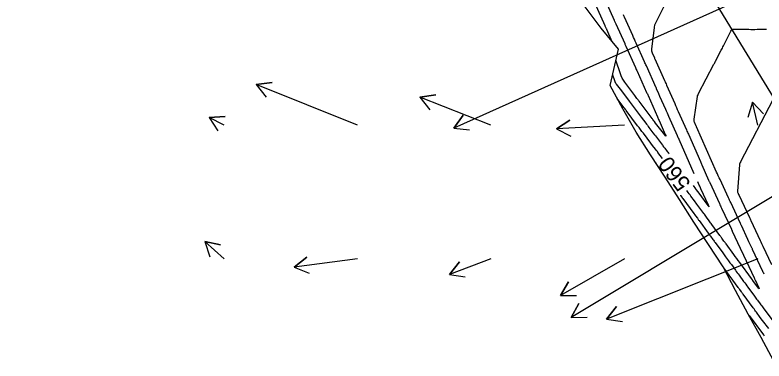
# Model space of a CAD drawing. Extents: x 954385 to 988206, y 1868364 to 1924553.
# Drawn here: x 956878.8 to 957159.4, y 1920780.6 to 1920910.1 of the extents above; entities that cross this region are included whole.
import ezdxf

# ---------------------------------------------------------------- set-up
doc = ezdxf.new("R2010")
doc.units = 0
for name, color, linetype in [('24', 7, 'Continuous'), ('26', 7, 'Continuous'), ('5', 7, 'Continuous'), ('6', 7, 'Continuous'), ('7', 7, 'Continuous'), ('Default', 7, 'Continuous')]:
    doc.layers.add(name, color=color, linetype=linetype)

msp = doc.modelspace()

# ---------------------------------------------------------------- linework, layer by layer
at = {"layer": '24'}
msp.add_lwpolyline([(957163.12, 1920780.62), (957158.31, 1920789.4), (957153.5, 1920798.19), (957148.78, 1920807.02), (957144.15, 1920815.91), (957138.58, 1920824.23), (957133.17, 1920832.64), (957127.8, 1920841.08), (957122.33, 1920849.45), (957116.87, 1920857.84), (957111.47, 1920866.26), (957106.54, 1920874.96), (957101.74, 1920883.75), (957104.85, 1920897.38), (957098.4, 1920905.15), (957092.36, 1920913.18)], dxfattribs=at)
at = {"layer": '26'}
for points in [[(957157.13, 1920918.93), (957043.17, 1920867.81), (957046.68, 1920872.67), (957043.17, 1920867.81), (957049.13, 1920867.2)], [(957007.13, 1920868.93), (956969.15, 1920884.07), (956975.09, 1920884.93), (956969.15, 1920884.07), (956972.87, 1920879.36)], [(957057.13, 1920868.93), (957030.49, 1920879.36), (957036.42, 1920880.26), (957030.49, 1920879.36), (957034.23, 1920874.67)], [(957157.13, 1920868.93), (957155.14, 1920877.47), (957159.24, 1920873.09), (957155.14, 1920877.47), (957153.4, 1920871.73)], [(956957.13, 1920868.93), (956951.55, 1920871.78), (956957.54, 1920872.09), (956951.55, 1920871.78), (956954.81, 1920866.74)], [(957107.13, 1920868.93), (957081.65, 1920867.47), (957086.66, 1920870.76), (957081.65, 1920867.47), (957087, 1920864.77)], [(957207.13, 1920868.93), (957087.13, 1920796.9), (957090.04, 1920802.14), (957087.13, 1920796.9), (957093.13, 1920797)], [(956957.13, 1920818.93), (956949.95, 1920825.3), (956955.83, 1920824.09), (956949.95, 1920825.3), (956951.85, 1920819.6)], [(957007.13, 1920818.93), (956983.42, 1920815.77), (956988.18, 1920819.43), (956983.42, 1920815.77), (956988.97, 1920813.48)], [(957057.13, 1920818.93), (957041.56, 1920813.05), (957045.36, 1920817.69), (957041.56, 1920813.05), (957047.48, 1920812.08)], [(957107.13, 1920818.93), (957083.18, 1920805.09), (957086.18, 1920810.29), (957083.18, 1920805.09), (957089.18, 1920805.09)], [(957157.13, 1920818.93), (957100.44, 1920796.32), (957104.15, 1920801.03), (957100.44, 1920796.32), (957106.38, 1920795.46)]]:
    msp.add_lwpolyline(points, dxfattribs=at)
at = {"layer": '6'}
for points in [[(957125.98, 1920921.71), (957118.38, 1920906.33), (957118.36, 1920906.29), (957118.35, 1920906.26), (957118.34, 1920906.22), (957118.34, 1920906.19), (957118.27, 1920905.68), (957118.26, 1920905.58), (957118.25, 1920905.48), (957117.28, 1920897.39), (957117.26, 1920897.02), (957117.29, 1920896.67), (957117.37, 1920896.32), (957117.49, 1920895.98), (957118.33, 1920894.13), (957118.37, 1920894.04), (957118.41, 1920893.95), (957118.45, 1920893.86), (957118.49, 1920893.77), (957122.17, 1920885.56), (957122.35, 1920885.15), (957122.53, 1920884.75), (957122.71, 1920884.34), (957122.89, 1920883.93), (957125.96, 1920877), (957126.29, 1920876.26), (957126.62, 1920875.52), (957126.94, 1920874.78), (957127.27, 1920874.05), (957130.33, 1920867.13), (957130.52, 1920866.71), (957130.7, 1920866.3), (957130.89, 1920865.88), (957131.07, 1920865.47), (957135.59, 1920855.25), (957136, 1920854.33), (957136.13, 1920854.03), (957138.68, 1920848.27), (957138.77, 1920848.06), (957138.87, 1920847.85), (957138.97, 1920847.64), (957139.06, 1920847.43), (957142.72, 1920839.55), (957142.91, 1920839.13), (957143.1, 1920838.72), (957143.3, 1920838.3), (957143.49, 1920837.89), (957147.21, 1920829.94), (957147.29, 1920829.77), (957147.37, 1920829.6), (957147.45, 1920829.44), (957147.53, 1920829.27), (957151.51, 1920820.76), (957151.57, 1920820.62), (957151.63, 1920820.49), (957151.7, 1920820.36), (957151.76, 1920820.22), (957155.73, 1920811.75), (957155.81, 1920811.56), (957155.9, 1920811.38), (957155.99, 1920811.19), (957156.07, 1920811.01), (957157.47, 1920807.99), (957157.57, 1920807.74), (957157.58, 1920807.65), (957157.51, 1920807.71), (957157.34, 1920807.91), (957155.22, 1920810.78), (957155.18, 1920810.84), (957155.13, 1920810.91), (957155.09, 1920810.97), (957155.04, 1920811.03), (957154.68, 1920811.53), (957150.3, 1920817.5), (957149.75, 1920818.25), (957149.2, 1920819), (957148.65, 1920819.75), (957148.1, 1920820.5), (957145.18, 1920824.48), (957144.99, 1920824.74), (957144.8, 1920825), (957144.61, 1920825.26), (957144.41, 1920825.52), (957143.65, 1920826.57), (957143.45, 1920826.83), (957143.26, 1920827.09), (957143.07, 1920827.35), (957142.88, 1920827.61), (957139.89, 1920831.69), (957139.64, 1920832.04), (957139.38, 1920832.39), (957139.12, 1920832.74), (957138.87, 1920833.09), (957137.84, 1920834.48), (957137.59, 1920834.83), (957137.33, 1920835.18), (957137.07, 1920835.53), (957136.81, 1920835.88), (957134.62, 1920838.86), (957134.29, 1920839.3), (957133.97, 1920839.74), (957133.64, 1920840.18), (957133.32, 1920840.62), (957132.02, 1920842.38), (957131.7, 1920842.82), (957131.37, 1920843.26), (957131.04, 1920843.7), (957130.71, 1920844.13), (957130.45, 1920844.47)], [(957121.39, 1920856.43), (957119.67, 1920858.7), (957119.45, 1920858.99), (957119.23, 1920859.28), (957119.01, 1920859.57), (957118.79, 1920859.86), (957117.69, 1920861.31), (957117.03, 1920862.19), (957114.24, 1920865.87), (957113.7, 1920866.58), (957113.16, 1920867.29), (957112.62, 1920868), (957112.08, 1920868.71), (957107.75, 1920874.42), (957107.62, 1920874.6), (957107.49, 1920874.77), (957107.22, 1920875.12), (957107.16, 1920875.21), (957107.09, 1920875.3), (957107.02, 1920875.39), (957106.96, 1920875.47), (957104.41, 1920878.86)]]:
    msp.add_lwpolyline(points, dxfattribs=at)
at = {"layer": '7'}
for points in [[(957099.49, 1920916.65), (957103.27, 1920908.23), (957103.31, 1920908.15), (957103.34, 1920908.08), (957103.89, 1920906.85), (957107.23, 1920899.44), (957107.33, 1920899.2), (957107.44, 1920898.96), (957107.55, 1920898.72), (957107.66, 1920898.48), (957111.26, 1920890.48), (957111.42, 1920890.13), (957111.58, 1920889.77), (957111.74, 1920889.42), (957111.9, 1920889.06), (957115.44, 1920881.17), (957115.57, 1920880.87), (957115.71, 1920880.57), (957115.84, 1920880.27), (957115.97, 1920879.98), (957119.49, 1920872.03), (957119.64, 1920871.69), (957119.79, 1920871.35), (957119.94, 1920871), (957120.09, 1920870.66), (957122.44, 1920865.37), (957122.6, 1920864.97), (957122.61, 1920864.81), (957122.48, 1920864.9), (957122.21, 1920865.24), (957118.82, 1920869.7), (957118.4, 1920870.26), (957118.28, 1920870.42), (957118.16, 1920870.58), (957117.81, 1920871.04), (957117.66, 1920871.24), (957117.5, 1920871.45), (957112.59, 1920877.92), (957112.4, 1920878.18), (957112.21, 1920878.43), (957112.02, 1920878.68), (957111.83, 1920878.94), (957111.06, 1920879.95), (957110.68, 1920880.46), (957110.3, 1920880.97), (957107.24, 1920885.03), (957106.74, 1920885.76), (957106.29, 1920886.52), (957105.92, 1920887.32), (957105.6, 1920888.15), (957103.91, 1920893.22)], [(957102.57, 1920900.13), (957100.5, 1920904.72), (957100.47, 1920904.79), (957100.41, 1920904.92), (957100.4, 1920904.94), (957099.92, 1920906), (957099.88, 1920906.1), (957099.86, 1920906.14), (957096.04, 1920914.64)], [(957133.28, 1920850.69), (957127.61, 1920863.48), (957127.45, 1920863.85), (957127.29, 1920864.21), (957127.13, 1920864.58), (957126.97, 1920864.94), (957123.78, 1920872.13), (957123.49, 1920872.78), (957123.2, 1920873.43), (957122.91, 1920874.09), (957122.63, 1920874.74), (957120.44, 1920879.68), (957120.04, 1920880.57), (957119.19, 1920882.49), (957119.16, 1920882.58), (957119.12, 1920882.66), (957119.08, 1920882.74), (957119.04, 1920882.83), (957115.35, 1920891.07), (957115.17, 1920891.46), (957115, 1920891.86), (957114.82, 1920892.25), (957114.64, 1920892.65), (957111.49, 1920899.64), (957111.17, 1920900.35), (957110.86, 1920901.05), (957110.54, 1920901.75), (957110.22, 1920902.45), (957107.12, 1920909.35), (957106.92, 1920909.79), (957106.72, 1920910.24)], [(957159.47, 1920813.13), (957159.31, 1920813.46), (957159.16, 1920813.8), (957159, 1920814.13), (957155.12, 1920822.41), (957155.05, 1920822.58), (957154.97, 1920822.74), (957153.78, 1920825.28), (957153.37, 1920826.16), (957150.95, 1920831.34), (957150.86, 1920831.52), (957150.78, 1920831.69), (957150.7, 1920831.87), (957150.62, 1920832.04), (957146.93, 1920839.93), (957146.72, 1920840.37), (957146.52, 1920840.81), (957146.31, 1920841.24), (957146.11, 1920841.68), (957142.93, 1920848.53), (957142.61, 1920849.24), (957142.29, 1920849.94), (957141.97, 1920850.64), (957141.65, 1920851.35), (957134.18, 1920868.23), (957134.11, 1920868.39), (957134.04, 1920868.54), (957133.38, 1920870.03), (957133.28, 1920870.31), (957133.22, 1920870.59), (957133.2, 1920870.88), (957133.23, 1920871.17), (957134.46, 1920879.69), (957134.48, 1920879.78), (957134.5, 1920879.87), (957134.53, 1920879.96), (957134.57, 1920880.05), (957134.75, 1920880.38), (957134.79, 1920880.47), (957134.84, 1920880.55), (957134.88, 1920880.64), (957134.92, 1920880.72), (957140.66, 1920891.72), (957140.81, 1920892), (957140.96, 1920892.29), (957141.11, 1920892.58), (957141.26, 1920892.86), (957143.4, 1920896.98), (957143.61, 1920897.37), (957143.82, 1920897.77), (957144.02, 1920898.17), (957144.22, 1920898.58), (957146.98, 1920904.07), (957147.2, 1920904.4), (957147.47, 1920904.64), (957147.81, 1920904.78), (957148.2, 1920904.82), (957153.7, 1920904.78), (957154.48, 1920904.77), (957155.25, 1920904.77), (957156.02, 1920904.77), (957156.79, 1920904.78), (957160.34, 1920904.81)], [(957102.66, 1920887.74), (957103.37, 1920885.61), (957103.5, 1920885.26), (957103.66, 1920884.92), (957103.85, 1920884.6), (957104.06, 1920884.29), (957105.04, 1920883), (957105.51, 1920882.36), (957105.99, 1920881.73), (957108.91, 1920877.85), (957109.28, 1920877.36), (957109.65, 1920876.87), (957110.02, 1920876.37), (957110.4, 1920875.88), (957111.89, 1920873.91), (957112.27, 1920873.41), (957112.64, 1920872.92), (957113.01, 1920872.43), (957113.39, 1920871.93), (957115.12, 1920869.65), (957115.42, 1920869.25), (957115.72, 1920868.86), (957116.02, 1920868.46), (957116.32, 1920868.07), (957117.82, 1920866.09), (957118.42, 1920865.3), (957118.72, 1920864.9), (957121.34, 1920861.44), (957121.56, 1920861.14), (957121.79, 1920860.85), (957122.02, 1920860.55), (957122.24, 1920860.25), (957123.15, 1920859.05), (957123.38, 1920858.75), (957123.6, 1920858.45), (957123.77, 1920858.23)], [(957162.75, 1920878.35), (957150.64, 1920855.12), (957150.61, 1920855.07), (957150.58, 1920855.01), (957150.55, 1920854.96), (957150.53, 1920854.9), (957150.25, 1920854.27), (957150.23, 1920854.23), (957150.22, 1920854.18), (957150.21, 1920854.13), (957150.2, 1920854.08), (957149.46, 1920844.23), (957149.46, 1920844.08), (957149.48, 1920843.94), (957149.51, 1920843.81), (957149.56, 1920843.68), (957149.9, 1920842.95), (957149.91, 1920842.92), (957149.93, 1920842.89), (957149.94, 1920842.86), (957149.96, 1920842.83), (957153.92, 1920834.36), (957154.06, 1920834.07), (957154.19, 1920833.78), (957154.33, 1920833.49), (957154.47, 1920833.2), (957157.94, 1920825.77), (957158.2, 1920825.22), (957158.46, 1920824.67), (957158.72, 1920824.11), (957158.98, 1920823.56), (957162.18, 1920816.73)], [(957119.01, 1920854.62), (957118.65, 1920855.1)], [(957132.83, 1920846.28), (957133.8, 1920845.01), (957133.87, 1920844.92), (957133.93, 1920844.83), (957134, 1920844.74), (957134.06, 1920844.65), (957134.53, 1920844.02), (957134.59, 1920843.93), (957138.37, 1920838.81), (957138.7, 1920838.4), (957138.85, 1920838.28), (957138.82, 1920838.47), (957138.61, 1920838.96), (957135.77, 1920845.09), (957135.61, 1920845.42), (957135.46, 1920845.76), (957135.31, 1920846.1), (957135.15, 1920846.44), (957134.62, 1920847.64)], [(957128.08, 1920842.67), (957128.11, 1920842.63), (957128.61, 1920841.96), (957128.71, 1920841.83), (957128.81, 1920841.7), (957128.91, 1920841.56), (957129.01, 1920841.43), (957133.15, 1920835.81), (957133.48, 1920835.37), (957133.8, 1920834.93), (957134.45, 1920834.06), (957134.61, 1920833.84), (957134.77, 1920833.62), (957134.93, 1920833.4), (957135.09, 1920833.18), (957138.5, 1920828.53), (957138.72, 1920828.23), (957138.94, 1920827.93), (957139.16, 1920827.63), (957139.38, 1920827.33), (957140.26, 1920826.13), (957140.48, 1920825.83), (957140.7, 1920825.53), (957140.92, 1920825.23), (957141.14, 1920824.93), (957143.93, 1920821.13), (957144.2, 1920820.76), (957144.47, 1920820.39), (957144.74, 1920820.02), (957145.01, 1920819.65), (957146.1, 1920818.17), (957146.37, 1920817.8), (957146.64, 1920817.43), (957146.91, 1920817.06), (957147.18, 1920816.69), (957148.7, 1920814.62), (957149.04, 1920814.16), (957149.39, 1920813.69), (957149.73, 1920813.22), (957150.07, 1920812.75), (957151.78, 1920810.43), (957152.17, 1920809.88), (957152.57, 1920809.34), (957152.97, 1920808.8), (957153.37, 1920808.26), (957155.85, 1920804.91), (957156.12, 1920804.54), (957156.39, 1920804.18), (957156.66, 1920803.82), (957156.93, 1920803.45), (957158, 1920802), (957158.27, 1920801.63), (957158.54, 1920801.27), (957158.81, 1920800.91), (957159.08, 1920800.54), (957163.12, 1920795.14)], [(957161.18, 1920792.74), (957158.9, 1920795.8), (957158.02, 1920796.97), (957156.57, 1920798.92), (957156.27, 1920799.31), (957155.98, 1920799.7), (957155.69, 1920800.1), (957155.4, 1920800.49), (957151.57, 1920805.68), (957151.41, 1920805.89), (957151.26, 1920806.1), (957151.1, 1920806.31), (957150.95, 1920806.52), (957150.32, 1920807.36), (957150.17, 1920807.57), (957150.01, 1920807.78), (957149.86, 1920807.99), (957149.71, 1920808.2), (957144.4, 1920815.44)], [(957153.81, 1920797.62), (957159.18, 1920790.42), (957159.31, 1920790.26), (957159.43, 1920790.09)]]:
    msp.add_lwpolyline(points, dxfattribs=at)
at = {"layer": 'Default'}
msp.add_line((957221.14, 1920784.24), (956045.8, 1922705.18), dxfattribs=at)

# ---------------------------------------------------------------- texts
at = {"layer": '5'}
msp.add_text('560', height=6, rotation=127.1657, dxfattribs=at).set_placement((957132.2, 1920847.14))

doc.saveas('drawing.dxf')
